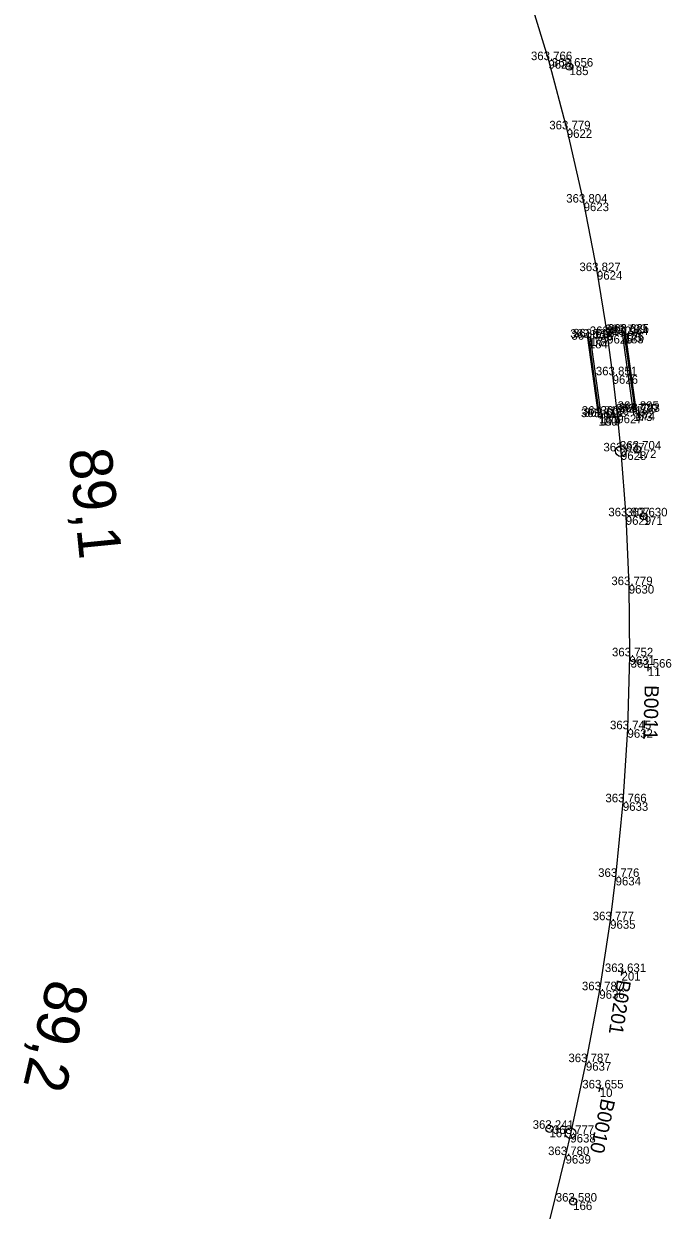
# Model space of a CAD drawing. Extents: x -599511 to -595511, y -1067427 to -1062061.
# Drawn here: x -595716.4 to -595625.3, y -1066933.1 to -1066766.1 of the extents above; entities that cross this region are included whole.
import ezdxf

# ---------------------------------------------------------------- set-up
doc = ezdxf.new("R2010")
doc.units = 0
for name, color, linetype in [('Vrstva 1', 7, 'Continuous'), ('Vrstva 17', 7, 'Continuous'), ('Vrstva 18', 7, 'Continuous'), ('Vrstva 50', 7, 'Continuous'), ('Vrstva 60', 7, 'Continuous'), ('Vrstva 61', 7, 'Continuous'), ('Vrstva 7', 7, 'Continuous')]:
    doc.layers.add(name, color=color, linetype=linetype)

msp = doc.modelspace()

# ---------------------------------------------------------------- linework, layer by layer
at = {"layer": 'Vrstva 1'}
msp.add_lwpolyline([(-595645.72, -1066760.82), (-595642.55, -1066771.26), (-595639.96, -1066781), (-595637.59, -1066791.31), (-595635.72, -1066800.95), (-595634.28, -1066809.94), (-595633.51, -1066815.61), (-595632.86, -1066821.15), (-595632.34, -1066826.32), (-595631.66, -1066835.45), (-595631.24, -1066845.14), (-595631.15, -1066855.16), (-595631.42, -1066865.42), (-595632.07, -1066875.7), (-595633.09, -1066886.2), (-595633.86, -1066892.3), (-595635.38, -1066902.15), (-595637.27, -1066912.27), (-595639.46, -1066922.38), (-595640.14, -1066925.35), (-595642.33, -1066934.34)], dxfattribs=at)
at = {"layer": 'Vrstva 17'}
for p, q in [((-595630.36, -1066820.47), (-595631.82, -1066809.92)), ((-595636.86, -1066810.61), (-595635.41, -1066821.16))]:
    msp.add_line(p, q, dxfattribs=at)
at = {"layer": 'Vrstva 18'}
for points in [[(-595635.51, -1066821.5), (-595635.09, -1066821.45), (-595636.63, -1066810.28), (-595637.03, -1066810.33)], [(-595630.59, -1066820.84), (-595632.11, -1066809.67), (-595631.74, -1066809.61), (-595630.2, -1066820.75)]]:
    msp.add_lwpolyline(points, close=True, dxfattribs=at)
at = {"layer": 'Vrstva 50'}
for p, q in [((-595639.61, -1066772.12), (-595639.58, -1066772.22)), ((-595629.14, -1066835.41), (-595629.14, -1066835.51)), ((-595639.05, -1066931.84), (-595639.08, -1066931.94))]:
    msp.add_line(p, q, dxfattribs=at)
for centre in [(-595639.59, -1066772.17), (-595629.14, -1066835.46), (-595639.06, -1066931.89)]:
    msp.add_circle(centre, 0.5, dxfattribs=at)
at = {"layer": 'Vrstva 60'}
for p, q in [((-595642.55, -1066771.26), (-595642.55, -1066771.26)), ((-595639.59, -1066772.17), (-595639.59, -1066772.17)), ((-595639.96, -1066781), (-595639.96, -1066781)), ((-595637.59, -1066791.31), (-595637.59, -1066791.31)), ((-595635.72, -1066800.95), (-595635.72, -1066800.95)), ((-595636.63, -1066810.28), (-595636.63, -1066810.28)), ((-595634.28, -1066809.94), (-595634.28, -1066809.94)), ((-595632.11, -1066809.67), (-595632.11, -1066809.67)), ((-595631.82, -1066809.92), (-595631.82, -1066809.92)), ((-595631.74, -1066809.61), (-595631.74, -1066809.61)), ((-595637.03, -1066810.33), (-595637.03, -1066810.33)), ((-595636.86, -1066810.61), (-595636.86, -1066810.61)), ((-595633.51, -1066815.61), (-595633.51, -1066815.61)), ((-595635.51, -1066821.5), (-595635.51, -1066821.5)), ((-595635.41, -1066821.16), (-595635.41, -1066821.16)), ((-595635.09, -1066821.45), (-595635.09, -1066821.45)), ((-595632.86, -1066821.15), (-595632.86, -1066821.15)), ((-595630.59, -1066820.84), (-595630.59, -1066820.84)), ((-595630.36, -1066820.47), (-595630.36, -1066820.47)), ((-595630.2, -1066820.75), (-595630.2, -1066820.75)), ((-595632.34, -1066826.32), (-595632.34, -1066826.32)), ((-595630.03, -1066826.06), (-595630.03, -1066826.06)), ((-595631.66, -1066835.45), (-595631.66, -1066835.45)), ((-595629.14, -1066835.46), (-595629.14, -1066835.46)), ((-595631.24, -1066845.14), (-595631.24, -1066845.14)), ((-595631.15, -1066855.16), (-595631.15, -1066855.16)), ((-595628.54, -1066856.75), (-595628.54, -1066856.75)), ((-595631.42, -1066865.42), (-595631.42, -1066865.42)), ((-595632.07, -1066875.7), (-595632.07, -1066875.7)), ((-595633.09, -1066886.2), (-595633.09, -1066886.2)), ((-595633.86, -1066892.3), (-595633.86, -1066892.3)), ((-595632.25, -1066899.59), (-595632.25, -1066899.59)), ((-595635.38, -1066902.15), (-595635.38, -1066902.15)), ((-595637.27, -1066912.27), (-595637.27, -1066912.27)), ((-595635.32, -1066915.97), (-595635.32, -1066915.97)), ((-595642.4, -1066921.65), (-595642.4, -1066921.65)), ((-595639.46, -1066922.38), (-595639.46, -1066922.38)), ((-595640.14, -1066925.35), (-595640.14, -1066925.35)), ((-595639.06, -1066931.89), (-595639.06, -1066931.89))]:
    msp.add_line(p, q, dxfattribs=at)
at = {"layer": 'Vrstva 7'}
for p, q in [((-595630.03, -1066826.01), (-595630.03, -1066826.11)), ((-595628.04, -1066856.76), (-595629.04, -1066856.74)), ((-595628.52, -1066856.25), (-595628.55, -1066857.25)), ((-595631.75, -1066899.67), (-595632.74, -1066899.52)), ((-595632.17, -1066899.1), (-595632.32, -1066900.09)), ((-595635.22, -1066915.48), (-595635.43, -1066916.46)), ((-595634.83, -1066916.07), (-595635.81, -1066915.86)), ((-595642.39, -1066921.6), (-595642.41, -1066921.7))]:
    msp.add_line(p, q, dxfattribs=at)
for centre, radius in [((-595632.35, -1066826.28), 0.75), ((-595630.03, -1066826.06), 0.5), ((-595642.4, -1066921.65), 0.5), ((-595639.43, -1066922.27), 0.75)]:
    msp.add_circle(centre, radius, dxfattribs=at)

# ---------------------------------------------------------------- texts
at = {"layer": 'Vrstva 60'}
for s, p in [('9621', (-595642.55, -1066772.46)), ('185', (-595639.59, -1066773.37)), ('9622', (-595639.96, -1066782.2)), ('9623', (-595637.59, -1066792.51)), ('9624', (-595635.72, -1066802.15)), ('177', (-595636.63, -1066811.48)), ('9625', (-595634.28, -1066811.14)), ('175', (-595632.11, -1066810.87)), ('183', (-595631.82, -1066811.12)), ('176', (-595631.74, -1066810.81)), ('178', (-595637.03, -1066811.53)), ('184', (-595636.86, -1066811.81)), ('9626', (-595633.51, -1066816.81)), ('180', (-595635.51, -1066822.7)), ('181', (-595635.41, -1066822.36)), ('179', (-595635.09, -1066822.65)), ('9627', (-595632.86, -1066822.35)), ('173', (-595630.59, -1066822.04)), ('182', (-595630.36, -1066821.67)), ('174', (-595630.2, -1066821.95)), ('9628', (-595632.34, -1066827.52)), ('172', (-595630.03, -1066827.26)), ('9629', (-595631.66, -1066836.65)), ('171', (-595629.14, -1066836.66)), ('9630', (-595631.24, -1066846.33)), ('9631', (-595631.15, -1066856.36)), ('11', (-595628.54, -1066857.95)), ('9632', (-595631.42, -1066866.62)), ('9633', (-595632.07, -1066876.9)), ('9634', (-595633.09, -1066887.4)), ('9635', (-595633.86, -1066893.5)), ('201', (-595632.25, -1066900.79)), ('9636', (-595635.38, -1066903.35)), ('9637', (-595637.27, -1066913.47)), ('10', (-595635.32, -1066917.17)), ('167', (-595642.4, -1066922.85)), ('9638', (-595639.46, -1066923.58)), ('9639', (-595640.14, -1066926.55)), ('166', (-595639.06, -1066933.09))]:
    msp.add_text(s, height=1.2, dxfattribs=at).set_placement(p)
at = {"layer": 'Vrstva 61'}
for s, p in [('363.766', (-595645, -1066771.26)), ('363.656', (-595642.05, -1066772.17)), ('363.779', (-595642.42, -1066781)), ('363.804', (-595640.04, -1066791.31)), ('363.827', (-595638.18, -1066800.95)), ('363.799', (-595634.56, -1066809.67)), ('363.825', (-595634.19, -1066809.61)), ('363.637', (-595639.48, -1066810.33)), ('364.733', (-595639.31, -1066810.61)), ('363.618', (-595639.08, -1066810.28)), ('363.850', (-595636.73, -1066809.94)), ('364.964', (-595634.27, -1066809.92)), ('363.851', (-595635.87, -1066815.61)), ('363.616', (-595637.97, -1066821.5)), ('364.712', (-595637.85, -1066821.16)), ('363.602', (-595637.54, -1066821.45)), ('363.841', (-595635.22, -1066821.15)), ('363.770', (-595633.04, -1066820.84)), ('364.895', (-595632.81, -1066820.47)), ('363.793', (-595632.66, -1066820.75)), ('363.837', (-595634.8, -1066826.32)), ('363.704', (-595632.48, -1066826.06)), ('363.807', (-595634.11, -1066835.45)), ('363.630', (-595631.59, -1066835.46)), ('363.779', (-595633.69, -1066845.14)), ('363.752', (-595633.6, -1066855.16)), ('363.566', (-595630.99, -1066856.75)), ('363.745', (-595633.88, -1066865.42)), ('363.766', (-595634.52, -1066875.7)), ('363.776', (-595635.55, -1066886.2)), ('363.777', (-595636.31, -1066892.3)), ('363.631', (-595634.6, -1066899.59)), ('363.787', (-595637.83, -1066902.15)), ('363.787', (-595639.73, -1066912.27)), ('363.655', (-595637.78, -1066915.97)), ('363.241', (-595644.76, -1066921.65)), ('363.777', (-595641.91, -1066922.38)), ('363.780', (-595642.59, -1066925.35)), ('363.580', (-595641.51, -1066931.89))]:
    msp.add_text(s, height=1.2, dxfattribs=at).set_placement(p)
at = {"layer": 'Vrstva 7'}
for s, height, rotation, p in [('89,1', 6, 275.7029, (-595710.04, -1066826.12)), ('B0011', 2, 268.4932, (-595629, -1066859.19)), ('89,2', 6, 257.011, (-595712.95, -1066900.37)), ('B0201', 2, 261.2551, (-595632.89, -1066900.57)), ('B0010', 2, 257.8232, (-595635.09, -1066917.28))]:
    msp.add_text(s, height=height, rotation=rotation, dxfattribs=at).set_placement(p)

doc.saveas('drawing.dxf')
